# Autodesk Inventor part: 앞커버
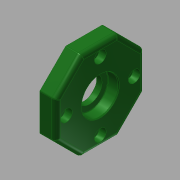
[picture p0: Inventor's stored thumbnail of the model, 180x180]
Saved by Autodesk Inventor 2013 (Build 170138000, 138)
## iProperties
Created: 2015-11
Part Number: 앞커버
Material: 알루미늄 6061
Document SubType Name: Modeling
Designer: mduedu
Density: 1 g/cm^3
Author: mduedu
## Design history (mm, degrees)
sketch "스케치5" dims "d66" = 60
  geometry: L1 (12.426, 30)-(30, 12.426); L2 (30, 12.426)-(30, -12.426); L3 (30, -12.426)-(12.426, -30); L4 (12.426, -30)-(-12.426, -30); L5 (-12.426, -30)-(-30, -12.426); L6 (-30, -12.426)-(-30, 12.426); L7 (-30, 12.426)-(-12.426, 30); L8 (-12.426, 30)-(12.426, 30); 4 further points
  constraints: 16 end point, 2 coincident, 2 vertical alignment, 1 midpoint, 19 other
extrude "돌출2" new body sketch "스케치5" distance "d67" = 11; taper "d68" = 0 deg
sketch "스케치6"
  geometry: C1 r 16 at (0, 0); 1 further point
  constraints: 1 centre point, 1 coincident
  dimensions: "d69" = 32 diameter of C1
extrude "돌출3" join sketch "스케치6" distance "d70" = 3; taper "d71" = 0 deg
hole "구멍7" diameter "d98" = 25; stored, may be unused: countersink angle "d102" = 90 deg, drill point angle "d104" = 0 deg; dims "d96" = 10, "d97" = 10, "d99" = 6, "d100" = 4, "d101" = 2, "d103" = 3
hole "구멍8" diameter "d107" = 25; stored, may be unused: countersink angle "d111" = 90 deg, drill point angle "d113" = 0 deg; dims "d108" = 6, "d109" = 4, "d110" = 2, "d112" = 7.3, "d143" = 10, "d144" = 10
hole "구멍9" diameter "d116" = 17; stored, may be unused: countersink angle "d120" = 90 deg, drill point angle "d122" = 0 deg; dims "d114" = 10, "d115" = 10, "d117" = 6, "d118" = 4, "d119" = 2, "d121" = 7.7
chamfer "모따기2" distance "d123" = 0.7; stored, may be unused: second distance "d124" = 2, angle "d125" = 30 deg
fillet "모깎기11" dims "d126" = 0.3
fillet "모깎기12" dims "d127" = 1
fillet "모깎기13" dims "d128" = 3
fillet "모깎기14" dims "d129" = 3
fillet "모깎기15" dims "d130" = 0.3
sketch "스케치8" dims "d131" = 46
  geometry: 3 further points
  constraints: 2 vertical alignment, 1 coincident, 2 other
hole "구멍10" sketch "스케치8" at (0, 23) diameter "d132" = 4.5; stored, may be unused: countersink angle "d136" = 90 deg, drill point angle "d138" = 0 deg; dims "d133" = 6, "d134" = 8, "d135" = 4.6, "d137" = 7.7
node "솔리드2"
pattern_circular "원형 패턴4" dims angle "d140" = 360 deg
